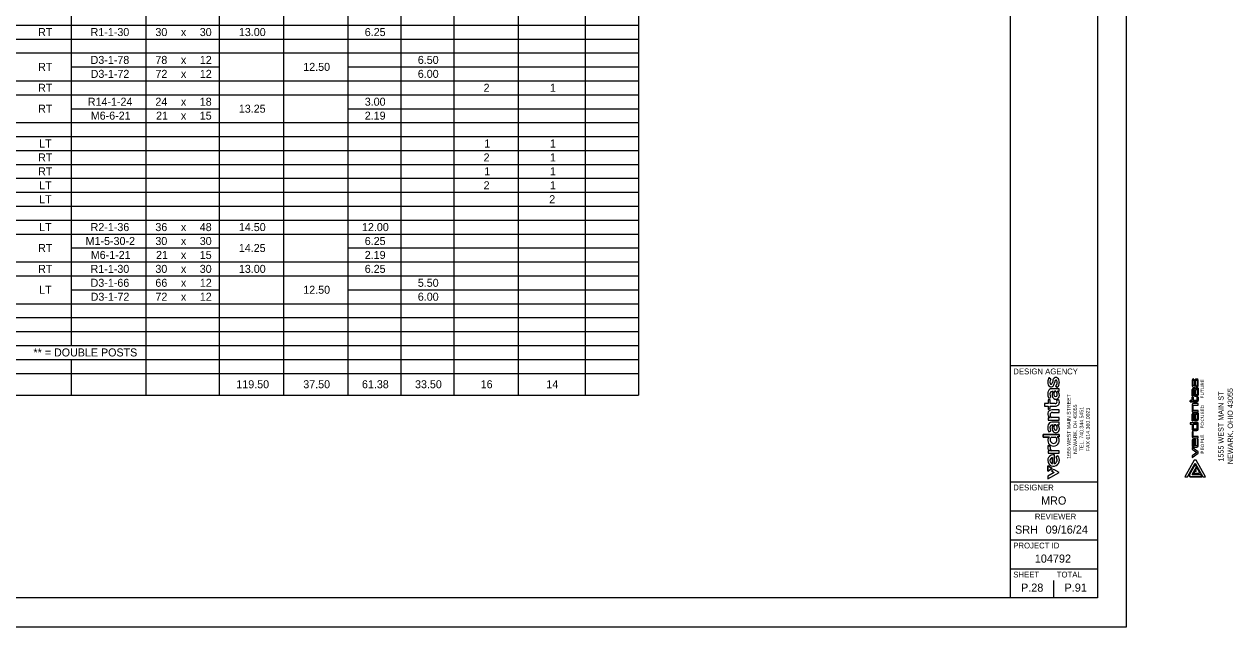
# Model space of a CAD drawing. Extents: x 0 to 35.9, y 0 to 22.
# Drawn here: x 15 to 35.85, y 0 to 10.38 of the extents above; entities that cross this region are included whole.
import ezdxf

# ---------------------------------------------------------------- set-up
doc = ezdxf.new("R2010")
doc.units = 0
for name, color, linetype in [('CS-ANNO-TTLB-LOGO', 7, 'Continuous'), ('Default', 7, 'Continuous'), ('SH_Border', 7, 'Continuous'), ('SH_Cut_Line', 7, 'Continuous'), ('SH_Data', 7, 'Continuous'), ('SH_Text', 7, 'Continuous')]:
    doc.layers.add(name, color=color, linetype=linetype)

msp = doc.modelspace()

# ---------------------------------------------------------------- linework, layer by layer
at = {"layer": 'CS-ANNO-TTLB-LOGO'}
for p, q in [((35.132, 4.247), (35.132, 4.154)), ((35.163, 4.269), (35.155, 4.269)), ((35.217, 4.269), (35.2, 4.269)), ((35.239, 4.154), (35.239, 4.247)), ((35.132, 3.974), (35.132, 4.086)), ((35.155, 4.131), (35.172, 4.131)), ((35.132, 3.549), (35.132, 3.661)), ((35.155, 3.38), (35.217, 3.38)), ((35.132, 3.209), (35.132, 3.119)), ((35.239, 3.119), (35.239, 3.231)), ((35.155, 3.096), (35.217, 3.096))]:
    msp.add_line(p, q, dxfattribs=at)
for points in [[(35.177, 4.247), (35.177, 4.159), (35.152, 4.159), (35.152, 4.247), (35.163, 4.247), (35.163, 4.269)], [(35.194, 4.154), (35.194, 4.247), (35.22, 4.247), (35.22, 4.159), (35.211, 4.159), (35.211, 4.131), (35.217, 4.131)], [(35.217, 3.974), (35.177, 3.974), (35.177, 4.086), (35.152, 4.086), (35.152, 3.974), (35.132, 3.974)], [(35.155, 4.109), (35.239, 4.109), (35.239, 3.996)], [(35.098, 3.898), (35.132, 3.898), (35.132, 3.954), (35.152, 3.954), (35.152, 3.898), (35.22, 3.898), (35.22, 3.954), (35.239, 3.954), (35.239, 3.898)], [(35.217, 3.875), (35.098, 3.875), (35.098, 3.898)], [(35.132, 3.825), (35.132, 3.706), (35.239, 3.706), (35.239, 3.729), (35.152, 3.729), (35.152, 3.819), (35.239, 3.819)], [(35.239, 3.819), (35.239, 3.847), (35.155, 3.847)], [(35.217, 3.549), (35.177, 3.549), (35.177, 3.661), (35.152, 3.661), (35.152, 3.549), (35.132, 3.549)], [(35.155, 3.684), (35.239, 3.684), (35.239, 3.571)], [(35.098, 3.515), (35.098, 3.493), (35.132, 3.493), (35.132, 3.403)], [(35.239, 3.403), (35.239, 3.515), (35.098, 3.515)], [(35.239, 3.279), (35.152, 3.279), (35.152, 3.358), (35.132, 3.358), (35.132, 3.279)], [(35.155, 3.256), (35.239, 3.256), (35.239, 3.279)], [(35.239, 3.231), (35.22, 3.231), (35.22, 3.119), (35.194, 3.119), (35.194, 3.231), (35.155, 3.231)]]:
    msp.add_lwpolyline(points, dxfattribs=at)
for points in [[(35.194, 4.086), (35.22, 4.086), (35.22, 3.996), (35.194, 3.996)], [(35.194, 3.661), (35.22, 3.661), (35.22, 3.571), (35.194, 3.571)], [(35.152, 3.493), (35.152, 3.403), (35.22, 3.403), (35.22, 3.493)], [(35.177, 3.209), (35.152, 3.209), (35.152, 3.119), (35.177, 3.119)], [(35.217, 3.002), (35.132, 2.943), (35.132, 2.916), (35.239, 2.991), (35.24, 3.014), (35.133, 3.089), (35.132, 3.062)]]:
    msp.add_lwpolyline(points, close=True, dxfattribs=at)
for centre, start, end in [((35.155, 4.247), 90, 180), ((35.2, 4.247), 90, 180), ((35.217, 4.247), 360, 90), ((35.155, 4.154), 180, 270), ((35.155, 4.086), 90, 180), ((35.172, 4.154), 270, 0), ((35.217, 4.154), 270, 0), ((35.217, 3.996), 270, 360), ((35.155, 3.825), 90, 180), ((35.217, 3.898), 270, 360), ((35.155, 3.661), 90, 180), ((35.217, 3.571), 270, 360), ((35.155, 3.403), 180, 270), ((35.217, 3.403), 270, 0), ((35.155, 3.279), 180, 270), ((35.155, 3.209), 90, 180), ((35.155, 3.119), 180, 270), ((35.217, 3.119), 270, 0)]:
    msp.add_arc(centre, 0.0225, start, end, dxfattribs=at)
at = {"layer": 'Default'}
for p, q in [((35.132, 4.247), (35.132, 4.154)), ((35.217, 4.269), (35.2, 4.269)), ((35.239, 4.154), (35.239, 4.247)), ((35.155, 4.131), (35.172, 4.131)), ((35.155, 3.38), (35.217, 3.38)), ((35.132, 3.209), (35.132, 3.119)), ((35.155, 3.096), (35.217, 3.096)), ((35.082, 2.612), (35.185, 2.795)), ((35.208, 2.755), (35.134, 2.624)), ((35.185, 2.795), (35.208, 2.755)), ((35.098, 2.585), (35.082, 2.612)), ((35.304, 2.585), (35.098, 2.585)), ((35.134, 2.624), (35.282, 2.624)), ((35.282, 2.624), (35.304, 2.585))]:
    msp.add_line(p, q, dxfattribs=at)
for points in [[(35.177, 4.247), (35.177, 4.159), (35.152, 4.159), (35.152, 4.247), (35.163, 4.247), (35.163, 4.269), (35.155, 4.269)], [(35.194, 4.154), (35.194, 4.247), (35.22, 4.247), (35.22, 4.159), (35.211, 4.159), (35.211, 4.131), (35.217, 4.131)], [(35.132, 4.086), (35.132, 3.974), (35.152, 3.974), (35.152, 4.086), (35.177, 4.086), (35.177, 3.974), (35.217, 3.974)], [(35.239, 3.996), (35.239, 4.109), (35.155, 4.109)], [(35.239, 3.898), (35.239, 3.954), (35.22, 3.954), (35.22, 3.898), (35.152, 3.898), (35.152, 3.954), (35.132, 3.954), (35.132, 3.898), (35.098, 3.898), (35.098, 3.875), (35.217, 3.875)], [(35.132, 3.825), (35.132, 3.706), (35.239, 3.706), (35.239, 3.729), (35.152, 3.729), (35.152, 3.819), (35.239, 3.819), (35.239, 3.847), (35.155, 3.847)], [(35.132, 3.661), (35.132, 3.549), (35.152, 3.549), (35.152, 3.661), (35.177, 3.661), (35.177, 3.549), (35.217, 3.549)], [(35.239, 3.571), (35.239, 3.684), (35.155, 3.684)], [(35.239, 3.403), (35.239, 3.515), (35.098, 3.515), (35.098, 3.493), (35.132, 3.493), (35.132, 3.403)], [(35.155, 3.256), (35.239, 3.256), (35.239, 3.279), (35.152, 3.279), (35.152, 3.358), (35.132, 3.358), (35.132, 3.279)], [(35.239, 3.119), (35.239, 3.231), (35.22, 3.231), (35.22, 3.119), (35.194, 3.119), (35.194, 3.231), (35.155, 3.231)]]:
    msp.add_lwpolyline(points, dxfattribs=at)
for points in [[(35.22, 4.086), (35.22, 3.996), (35.194, 3.996), (35.194, 4.086)], [(35.22, 3.661), (35.22, 3.571), (35.194, 3.571), (35.194, 3.661)], [(35.152, 3.493), (35.22, 3.493), (35.22, 3.403), (35.152, 3.403)], [(35.177, 3.209), (35.177, 3.119), (35.152, 3.119), (35.152, 3.209)], [(35.132, 2.943), (35.132, 2.916), (35.239, 2.991), (35.24, 3.014), (35.133, 3.089), (35.132, 3.062), (35.217, 3.002)], [(35.185, 2.818), (35.317, 2.585), (35.362, 2.585), (35.201, 2.87), (35.169, 2.87), (35.008, 2.585), (35.053, 2.585)], [(35.053, 2.585), (35.185, 2.818), (35.317, 2.585), (35.362, 2.585), (35.201, 2.87), (35.169, 2.87), (35.008, 2.585)], [(35.082, 2.612), (35.098, 2.585), (35.304, 2.585), (35.282, 2.624), (35.134, 2.624), (35.208, 2.755), (35.185, 2.795)], [(35.178, 2.68), (35.156, 2.641), (35.247, 2.641), (35.259, 2.664), (35.214, 2.744), (35.192, 2.704), (35.205, 2.68)], [(35.178, 2.68), (35.205, 2.68), (35.192, 2.704), (35.214, 2.744), (35.259, 2.664), (35.247, 2.641), (35.156, 2.641)]]:
    msp.add_lwpolyline(points, close=True, dxfattribs=at)
for centre, start, end in [((35.155, 4.247), 90, 180), ((35.2, 4.247), 90, 180), ((35.217, 4.247), 360, 90), ((35.155, 4.154), 180, 270), ((35.155, 4.086), 90, 180), ((35.172, 4.154), 270, 0), ((35.217, 4.154), 270, 0), ((35.217, 3.996), 270, 0), ((35.155, 3.825), 90, 180), ((35.217, 3.898), 270, 0), ((35.155, 3.661), 90, 180), ((35.217, 3.571), 270, 0), ((35.155, 3.403), 180, 270), ((35.217, 3.403), 270, 0), ((35.155, 3.279), 180, 270), ((35.155, 3.209), 90, 180), ((35.155, 3.119), 180, 270), ((35.217, 3.119), 270, 0)]:
    msp.add_arc(centre, 0.0225, start, end, dxfattribs=at)
at = {"layer": 'SH_Border'}
for p, q in [((32, 0.5), (32, 21.5)), ((32, 4.5), (33.5, 4.5)), ((32, 2.5), (33.5, 2.5)), ((32, 2), (33.5, 2)), ((32, 1.5), (33.5, 1.5)), ((32, 1), (33.5, 1))]:
    msp.add_line(p, q, dxfattribs=at)
msp.add_lwpolyline([(1.5, 21.5), (33.5, 21.5), (33.5, 0.5), (1.5, 0.5)], close=True, dxfattribs=at)
at = {"layer": 'SH_Cut_Line'}
msp.add_lwpolyline([(0, 0), (34, 0), (34, 22), (0, 22)], close=True, dxfattribs=at)
at = {"layer": 'SH_Data'}
for p, q in [((32.75, 3.5), (32.75, 3.5)), ((32.375, 0.675), (32.375, 0.675)), ((32.75, 0.5), (32.75, 0.8))]:
    msp.add_line(p, q, dxfattribs=at)
at = {"layer": 'SH_Text'}
for p, q in [((15.806, 17.807), (15.806, 4.847)), ((17.096, 17.807), (17.096, 3.992)), ((18.356, 17.807), (18.356, 3.992)), ((24.671, 17.807), (24.671, 3.992)), ((25.586, 17.807), (25.586, 3.992)), ((19.466, 17.447), (19.466, 3.992)), ((20.576, 17.447), (20.576, 3.992)), ((21.491, 17.447), (21.491, 3.992)), ((22.406, 17.447), (22.406, 3.992)), ((23.516, 17.447), (23.516, 3.992)), ((7.706, 10.367), (25.586, 10.367)), ((7.706, 10.127), (25.586, 10.127)), ((7.706, 9.887), (25.586, 9.887)), ((15.806, 9.647), (18.356, 9.647)), ((20.576, 9.647), (25.586, 9.647)), ((7.706, 9.407), (25.586, 9.407)), ((7.706, 9.167), (25.586, 9.167)), ((15.806, 8.927), (18.356, 8.927)), ((20.576, 8.927), (25.586, 8.927)), ((7.706, 8.687), (25.586, 8.687)), ((7.706, 8.447), (25.586, 8.447)), ((7.706, 8.207), (25.586, 8.207)), ((7.706, 7.967), (25.586, 7.967)), ((7.706, 7.727), (25.586, 7.727)), ((7.706, 7.487), (25.586, 7.487)), ((7.706, 7.247), (25.586, 7.247)), ((7.706, 7.007), (25.586, 7.007)), ((7.706, 6.767), (25.586, 6.767)), ((15.806, 6.527), (18.356, 6.527)), ((20.576, 6.527), (25.586, 6.527)), ((7.706, 6.287), (25.586, 6.287)), ((7.706, 6.047), (25.586, 6.047)), ((15.806, 5.807), (18.356, 5.807)), ((20.576, 5.807), (25.586, 5.807)), ((7.706, 5.567), (25.586, 5.567)), ((7.706, 5.327), (25.586, 5.327)), ((7.706, 5.087), (25.586, 5.087)), ((7.706, 4.847), (25.586, 4.847)), ((7.706, 4.607), (25.586, 4.607)), ((15.806, 4.607), (15.806, 3.992)), ((7.706, 4.367), (25.586, 4.367)), ((32.696, 4.265), (32.665, 4.288)), ((32.731, 4.239), (32.724, 4.208)), ((32.76, 4.197), (32.764, 4.217)), ((7.706, 3.992), (25.586, 3.992)), ((32.72, 4.057), (32.736, 4.057)), ((32.761, 4.057), (32.784, 4.057)), ((32.782, 4.149), (32.815, 4.125)), ((32.656, 3.949), (32.661, 3.937)), ((32.833, 3.913), (32.798, 3.897)), ((32.656, 3.37), (32.661, 3.358)), ((32.72, 3.478), (32.736, 3.478)), ((32.761, 3.478), (32.784, 3.478)), ((32.714, 3.27), (32.775, 3.27)), ((32.687, 3.099), (32.65, 3.121)), ((32.759, 2.81), (32.759, 2.963)), ((32.819, 2.948), (32.787, 2.926)), ((32.729, 2.918), (32.729, 2.811))]:
    msp.add_line(p, q, dxfattribs=at)
for points in [[(32.698, 4.267), (32.666, 4.29), (32.665, 4.288)], [(32.696, 4.265), (32.698, 4.267)], [(32.731, 4.239), (32.724, 4.208)], [(32.76, 4.197), (32.764, 4.217)], [(32.81, 4.06), (32.84, 4.06), (32.84, 4.102), (32.715, 4.102)], [(32.81, 4.06), (32.84, 4.06), (32.84, 4.102), (32.715, 4.102)], [(32.72, 4.057), (32.736, 4.057)], [(32.784, 4.057), (32.761, 4.057)], [(32.782, 4.149), (32.78, 4.147), (32.812, 4.122), (32.815, 4.125)], [(32.77, 3.847), (32.688, 3.847), (32.688, 3.908), (32.649, 3.908), (32.649, 3.847), (32.591, 3.847), (32.591, 3.802), (32.649, 3.802), (32.649, 3.742), (32.688, 3.765), (32.688, 3.802), (32.778, 3.802)], [(32.77, 3.847), (32.688, 3.847), (32.688, 3.908), (32.649, 3.908), (32.649, 3.847), (32.591, 3.847), (32.591, 3.802), (32.649, 3.802), (32.649, 3.742), (32.688, 3.765), (32.688, 3.802), (32.778, 3.802)], [(32.656, 3.949), (32.661, 3.937)], [(32.661, 3.937), (32.696, 3.951), (32.693, 3.961)], [(32.661, 3.937), (32.696, 3.951), (32.693, 3.961)], [(32.833, 3.913), (32.798, 3.897)], [(32.687, 3.603), (32.649, 3.603), (32.649, 3.561), (32.84, 3.561), (32.84, 3.607), (32.712, 3.607)], [(32.687, 3.603), (32.649, 3.603), (32.649, 3.561), (32.84, 3.561), (32.84, 3.607), (32.712, 3.607)], [(32.728, 3.693), (32.84, 3.693), (32.84, 3.738), (32.715, 3.738)], [(32.728, 3.693), (32.84, 3.693), (32.84, 3.738), (32.715, 3.738)], [(32.656, 3.37), (32.661, 3.358)], [(32.661, 3.358), (32.696, 3.373), (32.693, 3.382)], [(32.661, 3.358), (32.696, 3.373), (32.693, 3.382)], [(32.81, 3.482), (32.84, 3.482), (32.84, 3.524), (32.715, 3.524)], [(32.81, 3.482), (32.84, 3.482), (32.84, 3.524), (32.715, 3.524)], [(32.72, 3.478), (32.736, 3.478)], [(32.784, 3.478), (32.761, 3.478)], [(32.675, 3.27), (32.568, 3.27), (32.568, 3.315), (32.84, 3.315), (32.84, 3.274), (32.806, 3.274)], [(32.806, 3.274), (32.84, 3.274), (32.84, 3.315), (32.568, 3.315), (32.568, 3.27), (32.675, 3.27)], [(32.714, 3.27), (32.775, 3.27)], [(32.69, 3.031), (32.649, 3.031), (32.649, 2.99), (32.84, 2.99), (32.84, 3.034), (32.713, 3.034)], [(32.69, 3.031), (32.649, 3.031), (32.649, 2.99), (32.84, 2.99), (32.84, 3.034), (32.713, 3.034)], [(32.687, 3.099), (32.65, 3.121)], [(32.759, 2.81), (32.759, 2.963)], [(32.819, 2.948), (32.787, 2.926)], [(32.644, 2.773), (32.644, 2.682), (32.723, 2.728), (32.644, 2.773)], [(32.729, 2.811), (32.729, 2.918)], [(32.708, 2.686), (32.753, 2.66), (32.644, 2.598), (32.644, 2.548), (32.839, 2.66), (32.751, 2.711), (32.708, 2.686)]]:
    msp.add_lwpolyline(points, dxfattribs=at)
for points in [[(32.723, 2.728), (32.644, 2.682), (32.644, 2.773)], [(32.708, 2.686), (32.753, 2.66), (32.644, 2.598), (32.644, 2.548), (32.839, 2.66), (32.751, 2.711)]]:
    msp.add_lwpolyline(points, close=True, dxfattribs=at)
for centre, radius, start, end in [((32.776, 4.217), 0.131, 147.2233, 179.842), ((32.776, 4.217), 0.131, 147.2233, 179.842), ((32.758, 4.216), 0.114, 179.0109, 203.56), ((32.758, 4.216), 0.114, 179.0109, 203.56), ((32.777, 4.215), 0.0948, 148.1233, 178.1135), ((32.777, 4.215), 0.0948, 148.1233, 178.1135), ((32.752, 4.217), 0.0702, 179.0539, 195.6921), ((32.752, 4.217), 0.0702, 179.0539, 195.6921), ((32.717, 4.206), 0.0335, 193.8561, 223.7191), ((32.717, 4.206), 0.0335, 193.8561, 223.7191), ((32.703, 4.193), 0.0148, 224.7822, 330.4366), ((32.703, 4.193), 0.0148, 224.7822, 330.4366), ((32.643, 4.223), 0.0819, 332.9002, 349.3831), ((32.643, 4.223), 0.0819, 332.9002, 349.3831), ((32.857, 4.21), 0.13, 154.0447, 167.2149), ((32.857, 4.21), 0.13, 154.0447, 167.2149), ((32.656, 4.216), 0.105, 320.1259, 349.7023), ((32.656, 4.216), 0.105, 320.1259, 349.7023), ((32.785, 4.245), 0.0493, 52.7092, 154.2166), ((32.785, 4.245), 0.0493, 52.7092, 154.2166), ((32.858, 4.202), 0.0949, 158.1863, 170.6328), ((32.858, 4.202), 0.0949, 158.1863, 170.6328), ((32.785, 4.232), 0.0165, 26.9165, 163.602), ((32.785, 4.232), 0.0165, 26.9165, 163.602), ((32.714, 4.212), 0.0932, 317.363, 356.9244), ((32.714, 4.212), 0.0932, 317.363, 356.9244), ((32.742, 4.211), 0.0655, 357.0077, 26.3112), ((32.742, 4.211), 0.0655, 357.0077, 26.3112), ((32.77, 4.23), 0.0711, 22.8278, 50.7157), ((32.77, 4.23), 0.0711, 22.8278, 50.7157), ((32.715, 4.208), 0.129, 320.5166, 0.4341), ((32.715, 4.208), 0.129, 320.5166, 0.4341), ((32.725, 4.211), 0.12, 359.0192, 22.9257), ((32.725, 4.211), 0.12, 359.0192, 22.9257), ((32.772, 4.015), 0.128, 160.8128, 180.9317), ((32.772, 4.015), 0.128, 160.8128, 180.9317), ((32.843, 4.016), 0.199, 180.9467, 199.8354), ((32.843, 4.016), 0.199, 180.9467, 199.8354), ((32.712, 4.038), 0.0639, 88.076, 162.8642), ((32.712, 4.038), 0.0639, 88.076, 162.8642), ((32.715, 4.197), 0.067, 203.3692, 237.807), ((32.715, 4.197), 0.067, 203.3692, 237.807), ((32.703, 4.179), 0.0458, 238.9453, 317.6829), ((32.703, 4.179), 0.0458, 238.9453, 317.6829), ((32.747, 4.01), 0.0647, 163.2522, 179.9971), ((32.747, 4.01), 0.0647, 163.2522, 179.9971), ((32.834, 4.015), 0.152, 181.6616, 200.8714), ((32.834, 4.015), 0.152, 181.6616, 200.8714), ((32.722, 4.019), 0.0374, 92.9671, 165.223), ((32.722, 4.019), 0.0374, 92.9671, 165.223), ((32.828, 4), 0.108, 148.3497, 202.4708), ((32.828, 4), 0.108, 148.3497, 202.4708), ((32.855, 4.01), 0.105, 153.8372, 188.8746), ((32.855, 4.01), 0.105, 153.8372, 188.8746), ((32.78, 3.995), 0.0281, 182.327, 355.3778), ((32.78, 3.995), 0.0281, 182.327, 355.3778), ((32.745, 4.006), 0.0637, 348.1247, 52.3678), ((32.745, 4.006), 0.0637, 348.1247, 52.3678), ((32.759, 3.991), 0.0857, 338.2774, 53.7949), ((32.759, 3.991), 0.0857, 338.2774, 53.7949), ((32.783, 3.98), 0.0592, 201.6764, 339.7268), ((32.783, 3.98), 0.0592, 201.6764, 339.7268), ((32.773, 3.878), 0.0314, 265.0692, 356.3548), ((32.773, 3.878), 0.0314, 265.0692, 356.3548), ((32.78, 3.866), 0.0642, 267.8641, 1.6213), ((32.78, 3.866), 0.0642, 267.8641, 1.6213), ((32.761, 3.875), 0.0432, 1.8638, 29.9651), ((32.761, 3.875), 0.0432, 1.8638, 29.9651), ((32.751, 3.869), 0.0939, 359.5424, 28.2495), ((32.751, 3.869), 0.0939, 359.5424, 28.2495), ((32.714, 3.668), 0.0703, 88.9896, 246.9111), ((32.714, 3.668), 0.0703, 88.9896, 246.9111), ((32.728, 3.652), 0.0434, 137.3049, 182.9688), ((32.728, 3.652), 0.0434, 137.3049, 182.9688), ((32.733, 3.65), 0.0477, 180.3466, 244.9113), ((32.733, 3.65), 0.0477, 180.3466, 244.9113), ((32.726, 3.65), 0.0433, 86.9739, 132.7421), ((32.726, 3.65), 0.0433, 86.9739, 132.7421), ((32.772, 3.436), 0.128, 160.8128, 180.9317), ((32.772, 3.436), 0.128, 160.8128, 180.9317), ((32.843, 3.438), 0.199, 180.9467, 199.8354), ((32.843, 3.438), 0.199, 180.9467, 199.8354), ((32.712, 3.46), 0.0639, 88.076, 162.8642), ((32.712, 3.46), 0.0639, 88.076, 162.8642), ((32.747, 3.432), 0.0647, 163.2522, 179.9971), ((32.747, 3.432), 0.0647, 163.2522, 179.9971), ((32.834, 3.436), 0.152, 181.6616, 200.8714), ((32.834, 3.436), 0.152, 181.6616, 200.8714), ((32.722, 3.441), 0.0374, 92.9671, 165.223), ((32.722, 3.441), 0.0374, 92.9671, 165.223), ((32.828, 3.421), 0.108, 148.3497, 202.4708), ((32.828, 3.421), 0.108, 148.3497, 202.4708), ((32.783, 3.402), 0.0592, 201.6764, 339.7268), ((32.783, 3.402), 0.0592, 201.6764, 339.7268), ((32.855, 3.432), 0.105, 153.8372, 188.8746), ((32.855, 3.432), 0.105, 153.8372, 188.8746), ((32.78, 3.417), 0.0281, 182.327, 355.3778), ((32.78, 3.417), 0.0281, 182.327, 355.3778), ((32.745, 3.428), 0.0637, 348.1247, 52.3678), ((32.745, 3.428), 0.0637, 348.1247, 52.3678), ((32.759, 3.413), 0.0857, 338.2774, 53.7949), ((32.759, 3.413), 0.0857, 338.2774, 53.7949), ((32.716, 3.211), 0.0714, 124.2843, 181.2723), ((32.716, 3.211), 0.0714, 124.2843, 181.2723), ((32.744, 3.214), 0.1, 182.7719, 2.9779), ((32.744, 3.214), 0.1, 182.7719, 2.9779), ((32.743, 3.219), 0.0586, 119.9007, 175.5797), ((32.743, 3.219), 0.0586, 119.9007, 175.5797), ((32.744, 3.22), 0.0595, 176.4529, 5.055), ((32.744, 3.22), 0.0595, 176.4529, 5.055), ((32.745, 3.219), 0.0588, 6.0666, 60.041), ((32.745, 3.219), 0.0588, 6.0666, 60.041), ((32.777, 3.213), 0.0671, 5.3084, 64.5252), ((32.777, 3.213), 0.0671, 5.3084, 64.5252), ((32.706, 3.092), 0.0628, 152.6524, 255.2929), ((32.706, 3.092), 0.0628, 152.6524, 255.2929), ((32.744, 2.864), 0.0996, 81.0446, 280.2577), ((32.744, 2.864), 0.0996, 81.0446, 280.2577), ((32.739, 3.082), 0.0545, 162.1384, 242.0408), ((32.739, 3.082), 0.0545, 162.1384, 242.0408), ((32.734, 2.877), 0.072, 290.9232, 42.7391), ((32.734, 2.877), 0.072, 290.9232, 42.7391), ((32.731, 2.876), 0.114, 285.6668, 39.3699), ((32.731, 2.876), 0.114, 285.6668, 39.3699), ((32.737, 2.864), 0.0543, 98.8378, 261.1622), ((32.737, 2.864), 0.0543, 98.8378, 261.1622)]:
    msp.add_arc(centre, radius, start, end, dxfattribs=at)

# ---------------------------------------------------------------- texts
at = {"layer": 'Default'}
for s, p in [('E', (35.34, 4.212)), ('R', (35.34, 4.156)), ('U', (35.34, 4.095)), ('T', (35.34, 4.046)), ('U', (35.34, 3.986)), ('F', (35.34, 3.934)), ('D', (35.34, 3.764)), ('E', (35.34, 3.711)), ('S', (35.34, 3.659)), ('C', (35.34, 3.537)), ('U', (35.34, 3.6)), ('O', (35.34, 3.466)), ('F', (35.34, 3.417)), ('O', (35.34, 3.09)), ('E', (35.34, 3.259)), ('L', (35.34, 3.214)), ('P', (35.34, 3.161)), ('E', (35.34, 3.037)), ('P', (35.34, 2.984))]:
    msp.add_text(s, height=0.0563, rotation=90, dxfattribs=at).set_placement(p)
at = {"layer": 'SH_Data'}
for s, height, p in [('DESIGN AGENCY', 0.1, (32.05, 4.35)), ('DESIGNER', 0.1, (32.05, 2.35)), ('MRO', 0.14, (32.529, 2.105)), ('REVIEWER', 0.1, (32.422, 1.85)), ('SRH', 0.14, (32.08, 1.605)), ('09/16/24', 0.14, (32.608, 1.605)), ('PROJECT ID', 0.1, (32.05, 1.35)), ('104792', 0.14, (32.421, 1.105)), ('SHEET', 0.1, (32.05, 0.85)), ('TOTAL', 0.1, (32.8, 0.85)), ('P.28', 0.14, (32.183, 0.605)), ('P.91', 0.14, (32.934, 0.605))]:
    msp.add_text(s, height=height, dxfattribs=at).set_placement(p)
at = {"layer": 'SH_Text'}
for s, p in [('RT', (15.236, 10.178)), ('R1-1-30', (16.141, 10.178)), ('30', (17.258, 10.178)), ('x', (17.698, 10.178)), ('30', (18.023, 10.178)), ('13.00', (18.698, 10.178)), ('6.25', (20.868, 10.178)), ('D3-1-78', (16.141, 9.698)), ('78', (17.258, 9.698)), ('x', (17.698, 9.698)), ('12', (18.024, 9.698)), ('6.50', (21.783, 9.698)), ('RT', (15.236, 9.578)), ('D3-1-72', (16.142, 9.458)), ('72', (17.259, 9.458)), ('12', (18.024, 9.458)), ('12.50', (19.808, 9.578)), ('6.00', (21.783, 9.458)), ('x', (17.698, 9.458)), ('RT', (15.236, 9.218)), ('2', (22.917, 9.218)), ('1', (24.061, 9.218)), ('RT', (15.236, 8.858)), ('R14-1-24', (16.093, 8.978)), ('24', (17.258, 8.978)), ('x', (17.698, 8.978)), ('18', (18.023, 8.978)), ('13.25', (18.697, 8.858)), ('3.00', (20.868, 8.978)), ('M6-6-21', (16.144, 8.738)), ('21', (17.27, 8.738)), ('x', (17.698, 8.738)), ('15', (18.023, 8.738)), ('2.19', (20.868, 8.738)), ('LT', (15.255, 8.258)), ('1', (22.928, 8.258)), ('1', (24.061, 8.258)), ('RT', (15.236, 8.018)), ('2', (22.917, 8.018)), ('1', (24.061, 8.018)), ('RT', (15.236, 7.778)), ('1', (22.928, 7.778)), ('1', (24.061, 7.778)), ('LT', (15.255, 7.538)), ('2', (22.917, 7.538)), ('1', (24.061, 7.538)), ('LT', (15.255, 7.298)), ('2', (24.049, 7.298)), ('LT', (15.255, 6.818)), ('R2-1-36', (16.141, 6.818)), ('36', (17.258, 6.818)), ('x', (17.698, 6.818)), ('48', (18.023, 6.818)), ('14.50', (18.698, 6.818)), ('12.00', (20.82, 6.818)), ('M1-5-30-2', (16.055, 6.578)), ('30', (17.258, 6.578)), ('x', (17.698, 6.578)), ('30', (18.023, 6.578)), ('6.25', (20.868, 6.578)), ('RT', (15.236, 6.458)), ('M6-1-21', (16.144, 6.338)), ('21', (17.27, 6.338)), ('15', (18.023, 6.338)), ('14.25', (18.697, 6.458)), ('2.19', (20.868, 6.338)), ('x', (17.698, 6.338)), ('RT', (15.236, 6.098)), ('R1-1-30', (16.141, 6.098)), ('30', (17.258, 6.098)), ('x', (17.698, 6.098)), ('30', (18.023, 6.098)), ('13.00', (18.698, 6.098)), ('6.25', (20.868, 6.098)), ('LT', (15.255, 5.738)), ('D3-1-66', (16.141, 5.858)), ('66', (17.258, 5.858)), ('x', (17.698, 5.858)), ('12', (18.024, 5.858)), ('12.50', (19.808, 5.738)), ('5.50', (21.783, 5.858)), ('D3-1-72', (16.142, 5.618)), ('72', (17.259, 5.618)), ('x', (17.698, 5.618)), ('12', (18.024, 5.618)), ('6.00', (21.783, 5.618)), ('** = DOUBLE POSTS', (15.156, 4.658)), ('119.50', (18.654, 4.11)), ('37.50', (19.808, 4.11)), ('61.38', (20.82, 4.11)), ('33.50', (21.735, 4.11)), ('16', (22.867, 4.11)), ('14', (23.999, 4.11))]:
    msp.add_text(s, height=0.138, dxfattribs=at).set_placement(p)
for s, height, p in [('1555 WEST MAIN STREET', 0.06497, (33.039, 2.895)), ('1555 WEST MAIN ST', 0.09, (35.676, 2.846)), ('NEWARK, OHIO 43055', 0.09, (35.836, 2.8)), ('NEWARK, OH 43055', 0.06497, (33.149, 2.977)), ('TEL. 740.344.5451', 0.06497, (33.26, 3.026)), ('FAX 614.360.0023', 0.06497, (33.37, 3.026))]:
    msp.add_text(s, height=height, rotation=90, dxfattribs=at).set_placement(p)

doc.saveas('drawing.dxf')
